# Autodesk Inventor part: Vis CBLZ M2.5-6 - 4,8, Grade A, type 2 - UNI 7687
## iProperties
Created: 2002-05
Part Number: Vis CBLZ M2.5-6 - 4,8, Grade A, type 2 - UNI 7687
Material: Par défaut
Catalog Web Link: www.traceparts.com
Description: Vis CBLZ M2.5-6 - 4,8, Grade A, type 2 - UNI 7687
Document SubType Name: Modélisation
Designer: Flavien MARTY
Control State: 0
Master: False
Checked Out: False
Shininess: 20.0
Length Units: 11269
Angle Units: 11279
Time Units: 11290
Mass Units: 11283
Length Display Precision: 3
Angle Display Precision: 2
Compacted: True
Density: 0.0
Volumn: 0.0
Area: 0.0
PropertySet Name: Model Information
Author: Flavien MARTY
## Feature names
1. Base1
